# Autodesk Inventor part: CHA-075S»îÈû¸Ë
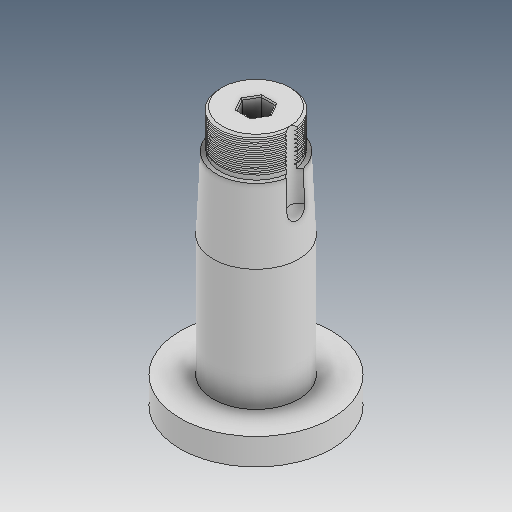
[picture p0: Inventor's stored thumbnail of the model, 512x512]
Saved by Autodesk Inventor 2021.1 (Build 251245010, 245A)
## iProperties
Created: 2019-12
Part Number: CHA-075S»îÈû¸Ë
Material: Ogólny
Document SubType Name: Modeling
Designer: user
Density: 1 g/cm^3
Appearance: Domyślna
Author: user
Revision Number: ÈÎºÎ
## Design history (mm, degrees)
feature "ÊäÈë1"
node "Bryła1"
